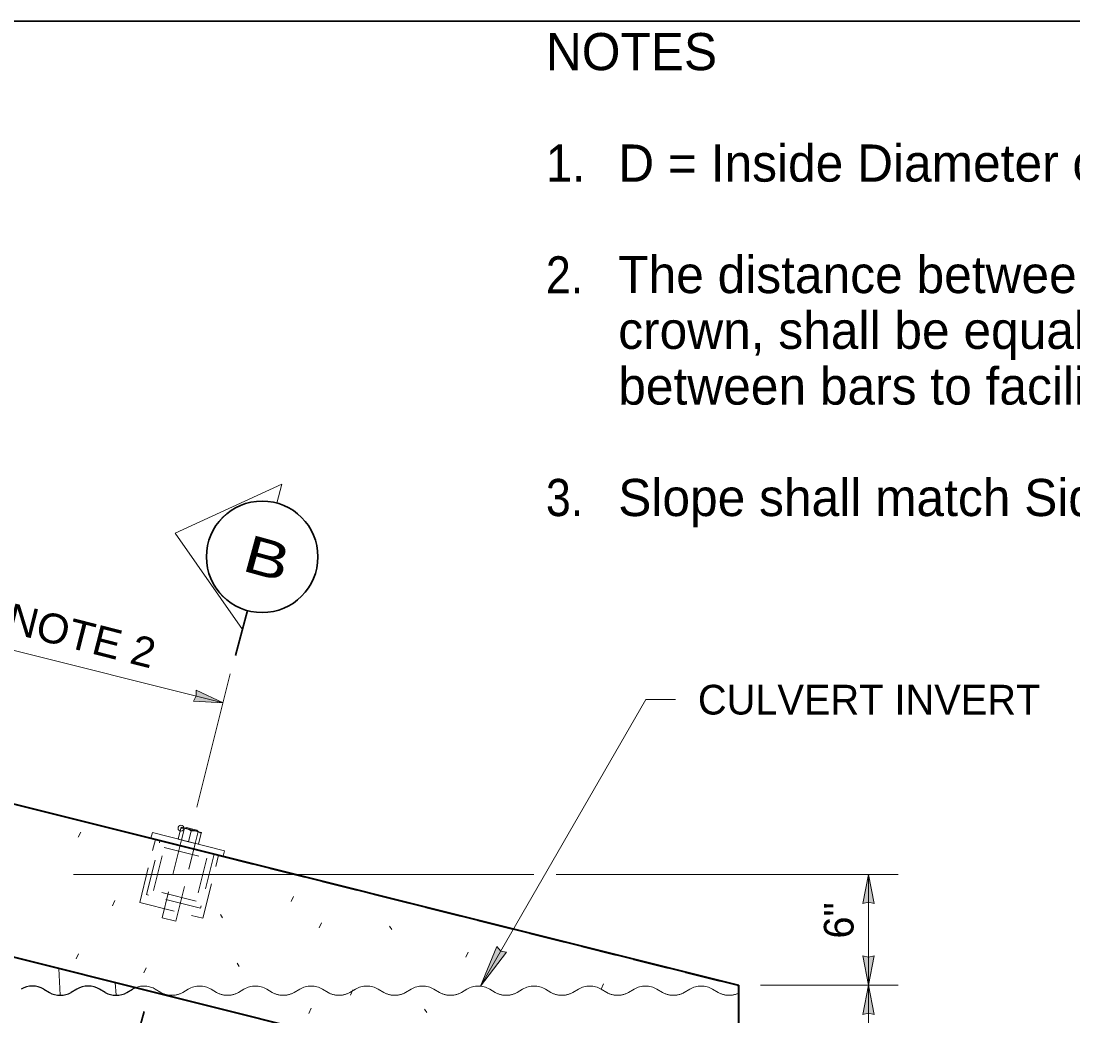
# Model space of a CAD drawing. Extents: x 99860 to 103153, y 99998 to 102077.
# Drawn here: x 101840 to 102406, y 101540 to 102076 of the extents above; entities that cross this region are included whole.
import ezdxf
from ezdxf.enums import TextEntityAlignment as Align

# ---------------------------------------------------------------- set-up
doc = ezdxf.new("R2010")
doc.units = 0
doc.header["$LTSCALE"] = 6.4
doc.header["$PDMODE"] = 32
doc.header["$PDSIZE"] = 3.2
doc.linetypes.add('MEDIUM_DASHED', pattern=[4.5, 3, -1.5])
for name, color, linetype, lineweight in [('1', 7, 'Continuous', 13), ('13', 7, 'Continuous', 40), ('15', 7, 'Continuous', 13), ('17', 7, 'Continuous', 13), ('20', 7, 'Continuous', 13), ('9', 7, 'Continuous', 13)]:
    doc.layers.add(name, color=color, linetype=linetype, lineweight=lineweight)

msp = doc.modelspace()

# ---------------------------------------------------------------- hatches: boundary and pattern name
at = {"layer": '15'}
for points in [[(101948.762, 101708.589), (101934.254, 101715.395), (101934.212, 101712.227), (101932.758, 101709.411)], [(102296.12, 101616.224), (102299.204, 101600.499), (102296.12, 101601.227), (102293.036, 101600.499)], [(102087.323, 101556.065), (102101.322, 101574.343), (102098.208, 101574.919), (102096.152, 101577.328)], [(102296.12, 101556.572), (102299.204, 101572.297), (102296.12, 101571.569), (102293.036, 101572.297)], [(102296.12, 101556.572), (102299.204, 101540.847), (102296.12, 101541.575), (102293.036, 101540.847)]]:
    msp.add_hatch(color=256, dxfattribs=at).paths.add_polyline_path(points)

# ---------------------------------------------------------------- linework, layer by layer
at = {"layer": '1', "linetype": 'MEDIUM_DASHED'}
for p, q in [((100938.07, 101796.125), (101898.063, 101556.125)), ((101726.451, 101681.49), (101912.331, 101635.02)), ((101903.842, 101601.065), (101912.331, 101635.02)), ((101907.48, 101605.31), (101914.756, 101634.414)), ((101909.905, 101635.627), (101948.711, 101625.925)), ((101946.286, 101626.531), (101912.331, 101635.02)), ((101914.756, 101634.414), (101943.86, 101627.138)), ((101911.27, 101607.583), (101917.03, 101630.624)), ((101917.03, 101630.624), (101940.071, 101624.864)), ((101940.071, 101624.864), (101934.31, 101601.823)), ((101943.86, 101627.138), (101936.584, 101598.034)), ((101946.204, 101626.205), (102226.12, 101556.125)), ((101946.286, 101626.531), (102226.12, 101556.572)), ((101934.31, 101601.823), (101911.27, 101607.583)), ((101936.584, 101598.034), (101907.48, 101605.31)), ((102226.12, 101556.572), (102226.12, 101556.125))]:
    msp.add_line(p, q, dxfattribs=at)
at = {"layer": '1'}
for p, q in [((101910.663, 101638.658), (101909.905, 101635.627)), ((101949.469, 101628.957), (101910.663, 101638.658)), ((101948.711, 101625.925), (101949.469, 101628.957)), ((101861.12, 101551.125), (101860.253, 101565.578)), ((101891.12, 101551.125), (101890.71, 101557.963))]:
    msp.add_line(p, q, dxfattribs=at)
at = {"layer": '1', "lineweight": 25}
for p, q in [((101852.259, 101554.439), (101855.246, 101552.662)), ((101869.982, 101554.439), (101866.995, 101552.662)), ((101885.246, 101552.662), (101882.259, 101554.439))]:
    msp.add_line(p, q, dxfattribs=at)
at = {"layer": '1', "lineweight": 35}
msp.add_lwpolyline([(99862, 99999.5), (103151, 99999.5), (103151, 102075.5), (99862, 102075.5)], close=True, dxfattribs=at)
at = {"layer": '1', "linetype": 'MEDIUM_DASHED'}
for points in [[(101903.842, 101601.065), (101937.797, 101592.577), (101946.286, 101626.531)], [(101912.258, 101554.437), (101912.259, 101554.439), (101915.246, 101552.662)], [(101926.995, 101552.662), (101929.982, 101554.439), (101929.983, 101554.437)], [(101942.258, 101554.437), (101942.259, 101554.439), (101945.246, 101552.662)], [(101956.995, 101552.662), (101959.982, 101554.439), (101959.983, 101554.437)], [(101972.258, 101554.437), (101972.259, 101554.439), (101975.246, 101552.662)], [(101986.995, 101552.662), (101989.982, 101554.439), (101989.983, 101554.437)], [(102002.258, 101554.437), (102002.259, 101554.439), (102005.246, 101552.662)], [(102016.995, 101552.662), (102019.982, 101554.439), (102019.983, 101554.437)], [(102032.258, 101554.437), (102032.259, 101554.439), (102035.246, 101552.662)], [(102046.995, 101552.662), (102049.982, 101554.439), (102049.983, 101554.437)], [(102062.258, 101554.437), (102062.259, 101554.439), (102065.246, 101552.662)], [(102076.995, 101552.662), (102079.982, 101554.439), (102079.983, 101554.437)], [(102092.258, 101554.437), (102092.259, 101554.439), (102095.246, 101552.662)], [(102106.995, 101552.662), (102109.982, 101554.439), (102109.983, 101554.437)], [(102122.258, 101554.437), (102122.259, 101554.439), (102125.246, 101552.662)], [(102136.995, 101552.662), (102139.982, 101554.439), (102139.983, 101554.437)], [(102152.258, 101554.437), (102152.259, 101554.439), (102155.246, 101552.662)], [(102166.995, 101552.662), (102169.982, 101554.439), (102169.983, 101554.437)], [(102182.258, 101554.437), (102182.259, 101554.439), (102185.246, 101552.662)], [(102196.995, 101552.662), (102199.982, 101554.439), (102199.983, 101554.437)], [(102212.258, 101554.437), (102212.259, 101554.439), (102215.246, 101552.662)]]:
    msp.add_lwpolyline(points, dxfattribs=at)
at = {"layer": '1', "lineweight": 25}
msp.add_lwpolyline([(101896.995, 101552.662), (101899.982, 101554.439), (101899.983, 101554.437)], dxfattribs=at)
for centre, start, end in [((101846.12, 101544.125), 59.24007, 120.75992), ((101876.12, 101544.125), 59.24007, 120.75993), ((101906.12, 101544.125), 112.47867, 120.75992), ((101861.12, 101563.125), 240.68709, 270), ((101861.12, 101563.125), 270, 299.31291), ((101891.12, 101563.125), 240.68709, 270), ((101891.12, 101563.125), 270, 299.31291)]:
    msp.add_arc(centre, 12, start, end, dxfattribs=at)
at = {"layer": '1', "linetype": 'MEDIUM_DASHED'}
for centre, start, end in [((101906.12, 101544.125), 59.24007, 111.66469), ((101936.12, 101544.125), 59.24007, 120.75993), ((101966.12, 101544.125), 59.24007, 120.75992), ((101996.12, 101544.125), 59.24007, 120.75993), ((102026.12, 101544.125), 59.24007, 120.75992), ((102056.12, 101544.125), 59.24007, 120.75993), ((102086.12, 101544.125), 59.24007, 120.75992), ((102116.12, 101544.125), 59.24007, 120.75993), ((102146.12, 101544.125), 59.24007, 120.75992), ((102176.12, 101544.125), 59.24007, 120.75993), ((102206.12, 101544.125), 59.24007, 120.75992), ((101921.12, 101563.125), 240.68709, 270), ((101921.12, 101563.125), 270, 299.31291), ((101951.12, 101563.125), 240.68709, 270), ((101951.12, 101563.125), 270, 299.31291), ((101981.12, 101563.125), 240.68709, 270), ((101981.12, 101563.125), 270, 299.31291), ((102011.12, 101563.125), 240.68709, 270), ((102011.12, 101563.125), 270, 299.31291), ((102041.12, 101563.125), 240.68709, 270), ((102041.12, 101563.125), 270, 299.31291), ((102071.12, 101563.125), 240.68709, 270), ((102071.12, 101563.125), 270, 299.31291), ((102101.12, 101563.125), 240.68709, 270), ((102101.12, 101563.125), 270, 299.31291), ((102131.12, 101563.125), 240.68709, 270), ((102131.12, 101563.125), 270, 299.31291), ((102161.12, 101563.125), 240.68709, 270), ((102161.12, 101563.125), 270, 299.31291), ((102191.12, 101563.125), 240.68709, 270), ((102191.12, 101563.125), 270, 299.31291), ((102221.12, 101563.125), 240.68709, 270), ((102221.12, 101563.125), 270, 294.58421)]:
    msp.add_arc(centre, 12, start, end, dxfattribs=at)
at = {"layer": '13'}
for p, q in [((100899.264, 101888.289), (102226.12, 101556.572)), ((102146.12, 101494.11), (100879.861, 101810.677)), ((102226.12, 101556.572), (102226.12, 101316.572))]:
    msp.add_line(p, q, dxfattribs=at)
at = {"layer": '15'}
for p, q in [((101948.762, 101708.589), (101728.927, 101763.548)), ((101952.642, 101724.112), (101934.695, 101652.321)), ((102087.323, 101556.065), (102176.341, 101710.247)), ((102176.342, 101710.247), (102192.342, 101710.247)), ((102116.056, 101616.224), (101868.23, 101616.224)), ((102312.12, 101616.224), (102128.056, 101616.224)), ((102296.12, 101616.224), (102296.12, 101556.572)), ((102238.084, 101556.572), (102312.12, 101556.572)), ((102296.12, 101556.572), (102296.12, 101316.572))]:
    msp.add_line(p, q, dxfattribs=at)
for points in [[(101948.762, 101708.589), (101934.254, 101715.395), (101934.212, 101712.227), (101932.758, 101709.411)], [(102296.12, 101616.224), (102299.204, 101600.499), (102296.12, 101601.227), (102293.036, 101600.499)], [(102087.323, 101556.065), (102101.322, 101574.343), (102098.208, 101574.919), (102096.152, 101577.328)], [(102296.12, 101556.572), (102299.204, 101572.297), (102296.12, 101571.569), (102293.036, 101572.297)], [(102296.12, 101556.572), (102299.204, 101540.847), (102296.12, 101541.575), (102293.036, 101540.847)]]:
    msp.add_lwpolyline(points, close=True, dxfattribs=at)
at = {"layer": '17'}
for p, q in [((101870.782, 101636.171), (101872.092, 101638.931)), ((101889.165, 101599.347), (101890.405, 101602.117)), ((101985.341, 101601.526), (101986.651, 101604.286)), ((101947.312, 101594.657), (101948.492, 101592.787)), ((102000.445, 101587.425), (102001.685, 101590.195)), ((102038.317, 101588.389), (102039.497, 101586.519)), ((101869.662, 101570.726), (101870.912, 101573.486)), ((102079.432, 101571.588), (102080.742, 101574.348)), ((101956.254, 101568.424), (101957.434, 101566.624)), ((101906.134, 101563.134), (101907.384, 101565.904)), ((102152.259, 101554.439), (102153.499, 101557.209)), ((102017.414, 101551.211), (102018.664, 101553.981)), ((101994.87, 101541.365), (101996.12, 101544.125)), ((102057.194, 101543.678), (102058.374, 101541.878))]:
    msp.add_line(p, q, dxfattribs=at)
at = {"layer": '9', "lineweight": 35}
for p, q in [((101961.926, 101758.174), (101955.375, 101734.047)), ((101906.258, 101542.452), (101893.155, 101494.199))]:
    msp.add_line(p, q, dxfattribs=at)
at = {"layer": '9'}
for p, q in [((101959.148, 101747.941), (101961.926, 101758.172)), ((101926.079, 101641.051), (101924.609, 101635.172)), ((101926.201, 101641.538), (101928.831, 101640.881)), ((101928.02, 101641.085), (101926.428, 101634.717)), ((101928.02, 101641.084), (101926.428, 101634.717)), ((101929.019, 101641.371), (101928.041, 101641.091)), ((101928.831, 101640.881), (101929.029, 101640.831)), ((101929.019, 101641.371), (101934.549, 101639.988)), ((101929.029, 101640.831), (101934.257, 101639.524)), ((101935.263, 101639.298), (101934.549, 101639.988)), ((101931.535, 101639.688), (101930.065, 101633.808)), ((101933.704, 101632.898), (101935.296, 101639.266)), ((101933.704, 101632.898), (101935.296, 101639.265)), ((101934.257, 101639.524), (101934.514, 101639.46)), ((101934.514, 101639.46), (101937.113, 101638.81)), ((101936.992, 101638.324), (101935.521, 101632.444))]:
    msp.add_line(p, q, dxfattribs=at)
at = {"layer": '9', "linetype": 'MEDIUM_DASHED'}
for p, q in [((101929.029, 101640.831), (101928.831, 101640.881)), ((101926.428, 101634.717), (101915.969, 101592.88)), ((101926.428, 101634.717), (101933.704, 101632.898)), ((101934.514, 101639.46), (101934.257, 101639.524)), ((101923.245, 101591.061), (101933.704, 101632.898)), ((101923.245, 101591.061), (101915.969, 101592.88))]:
    msp.add_line(p, q, dxfattribs=at)
at = {"layer": '9'}
msp.add_lwpolyline([(101977.65, 101816.074), (101980.428, 101826.305), (101923.019, 101799.824), (101959.148, 101747.941)], dxfattribs=at)
at = {"layer": '9', "linetype": 'MEDIUM_DASHED'}
msp.add_lwpolyline([(101924.609, 101635.172), (101930.065, 101633.808), (101935.521, 101632.444)], dxfattribs=at)
at = {"layer": '9', "lineweight": 35}
msp.add_circle((101969.787, 101787.124), 30, dxfattribs=at)
at = {"layer": '9'}
msp.add_arc((101969.787, 101787.124), 30, 74.80526, 254.80969, dxfattribs=at)
for points in [[(101926.201, 101641.538), (101926.201, 101641.538), (101926.198, 101641.527), (101926.192, 101641.504), (101926.175, 101641.437), (101926.134, 101641.272), (101926.079, 101641.051)], [(101926.079, 101641.051), (101926.096, 101641.122), (101926.113, 101641.186), (101926.127, 101641.244), (101926.173, 101641.428), (101926.201, 101641.538), (101926.201, 101641.538)], [(101926.079, 101641.051), (101927.003, 101641.123), (101927.94, 101641.09), (101928.831, 101640.881)], [(101935.296, 101639.266), (101935.296, 101639.266), (101935.282, 101639.27), (101935.256, 101639.277), (101935.195, 101639.292), (101935.064, 101639.326), (101934.873, 101639.374), (101934.683, 101639.422), (101934.428, 101639.486), (101934.129, 101639.561), (101933.83, 101639.636), (101933.479, 101639.724), (101933.106, 101639.817), (101932.732, 101639.911), (101932.325, 101640.013), (101931.919, 101640.114), (101931.513, 101640.216), (101931.096, 101640.32), (101930.703, 101640.418), (101930.31, 101640.516), (101929.931, 101640.611), (101929.595, 101640.695), (101929.26, 101640.778), (101928.96, 101640.853), (101928.72, 101640.913), (101928.479, 101640.972), (101928.293, 101641.018), (101928.175, 101641.047), (101928.073, 101641.073), (101928.02, 101641.085), (101928.02, 101641.085)], [(101929.029, 101640.831), (101929.058, 101640.824), (101929.088, 101640.815), (101929.118, 101640.807), (101929.969, 101640.57), (101930.78, 101640.169), (101931.535, 101639.688)], [(101931.535, 101639.688), (101932.449, 101639.758), (101933.375, 101639.728), (101934.257, 101639.524)], [(101934.514, 101639.46), (101934.534, 101639.455), (101934.554, 101639.449), (101934.573, 101639.444), (101935.425, 101639.207), (101936.236, 101638.805), (101936.992, 101638.324)], [(101936.992, 101638.324), (101937.009, 101638.394), (101937.025, 101638.459), (101937.04, 101638.516), (101937.083, 101638.691), (101937.11, 101638.799), (101937.113, 101638.81)]]:
    msp.add_open_spline(points, degree=3, dxfattribs=at)
at = {"layer": '9', "linetype": 'MEDIUM_DASHED'}
for points in [[(101931.535, 101639.687), (101930.67, 101640.238), (101929.727, 101640.682), (101928.738, 101640.901), (101927.875, 101641.092), (101926.971, 101641.12), (101926.079, 101641.051)], [(101928.02, 101641.085), (101928.02, 101641.085), (101928.021, 101641.085), (101928.024, 101641.084), (101928.042, 101641.079), (101928.13, 101641.056), (101928.282, 101641.018), (101928.433, 101640.98), (101928.652, 101640.925), (101928.92, 101640.857), (101929.189, 101640.79), (101929.513, 101640.708), (101929.868, 101640.619), (101930.222, 101640.531), (101930.616, 101640.432), (101931.017, 101640.332), (101931.418, 101640.231), (101931.837, 101640.127), (101932.239, 101640.026), (101932.641, 101639.926), (101933.037, 101639.827), (101933.395, 101639.738), (101933.619, 101639.682), (101933.831, 101639.629), (101934.024, 101639.581)], [(101928.234, 101641.03), (101928.282, 101641.018), (101928.339, 101641.004), (101928.403, 101640.987), (101928.585, 101640.942), (101928.832, 101640.879), (101929.124, 101640.806), (101929.416, 101640.733), (101929.761, 101640.646), (101930.131, 101640.553), (101930.501, 101640.461), (101930.905, 101640.36), (101931.31, 101640.258), (101931.715, 101640.157), (101932.133, 101640.053), (101932.528, 101639.954), (101932.924, 101639.855), (101933.308, 101639.759), (101933.649, 101639.674), (101933.989, 101639.589), (101934.296, 101639.513), (101934.544, 101639.451), (101934.772, 101639.395), (101934.955, 101639.349), (101935.082, 101639.318)], [(101935.082, 101639.318), (101935.076, 101639.319), (101935.071, 101639.321), (101935.066, 101639.322), (101934.923, 101639.357), (101934.713, 101639.409), (101934.452, 101639.474), (101934.191, 101639.539), (101933.873, 101639.618), (101933.523, 101639.706), (101933.174, 101639.793), (101932.783, 101639.89), (101932.384, 101639.99), (101931.985, 101640.089), (101931.567, 101640.194), (101931.163, 101640.295), (101930.76, 101640.396), (101930.361, 101640.496), (101929.998, 101640.587), (101929.771, 101640.644), (101929.556, 101640.698), (101929.358, 101640.747), (101929.043, 101640.826), (101928.767, 101640.896), (101928.555, 101640.949), (101928.426, 101640.982), (101928.318, 101641.009), (101928.234, 101641.03)], [(101934.324, 101639.508), (101934.281, 101639.518), (101934.238, 101639.528), (101934.195, 101639.537), (101933.332, 101639.729), (101932.428, 101639.756), (101931.535, 101639.687)], [(101934.024, 101639.581), (101934.334, 101639.504), (101934.602, 101639.437), (101934.806, 101639.386), (101935.01, 101639.336), (101935.156, 101639.3), (101935.232, 101639.281), (101935.274, 101639.271), (101935.296, 101639.266), (101935.296, 101639.266)], [(101936.991, 101638.324), (101936.199, 101638.827), (101935.346, 101639.244), (101934.449, 101639.476)]]:
    msp.add_open_spline(points, degree=3, dxfattribs=at)
at = {"layer": '9'}
msp.add_point((101926.079, 101641.051), dxfattribs=at)

# ---------------------------------------------------------------- texts
at = {"layer": '20'}
for s, height, p in [('NOTES', 20, (102122.519, 102049.052)), ('D = Inside Diameter of Culvert Pipe, or Pipe Arch Span Width, 36" maximum.', 20, (102161.444, 101989.052)), ('The distance between the safety bars, and between the top bar and the culvert', 20, (102161.444, 101929.052)), ('crown, shall be equal spaces of no more than 24".  The distance may vary ±1"', 20, (102161.444, 101899.052)), ('between bars to facilitate placement.', 20, (102161.444, 101869.052)), ('Slope shall match Side Slope; 6H:1V preferred, not steeper than 4H:1V.', 20, (102161.444, 101809.052)), ('CULVERT INVERT', 16, (102204.342, 101702.247))]:
    msp.add_text(s, height=height, dxfattribs=at).set_placement(p)
for s, width, p in [('1.', 0.95, (102122.519, 101989.052)), ('2.', 0.9, (102122.519, 101928.871)), ('3.', 0.9, (102122.519, 101809.052))]:
    msp.add_text(s, height=20, dxfattribs=dict(at, width=width)).set_placement(p)
for s, height, rotation, width, p in [('B', 20, 344.642, 1.35, (101969.788, 101776.753)), ('SEE NOTE 2', 16, 345.776, 1.05, (101845.746, 101743.231))]:
    msp.add_text(s, height=height, rotation=rotation, dxfattribs=dict(at, width=width)).set_placement(p, align=Align.CENTER)
msp.add_text('6"', height=16, rotation=90, dxfattribs=at).set_placement((102288.12, 101591.398), align=Align.CENTER)

doc.saveas('drawing.dxf')
